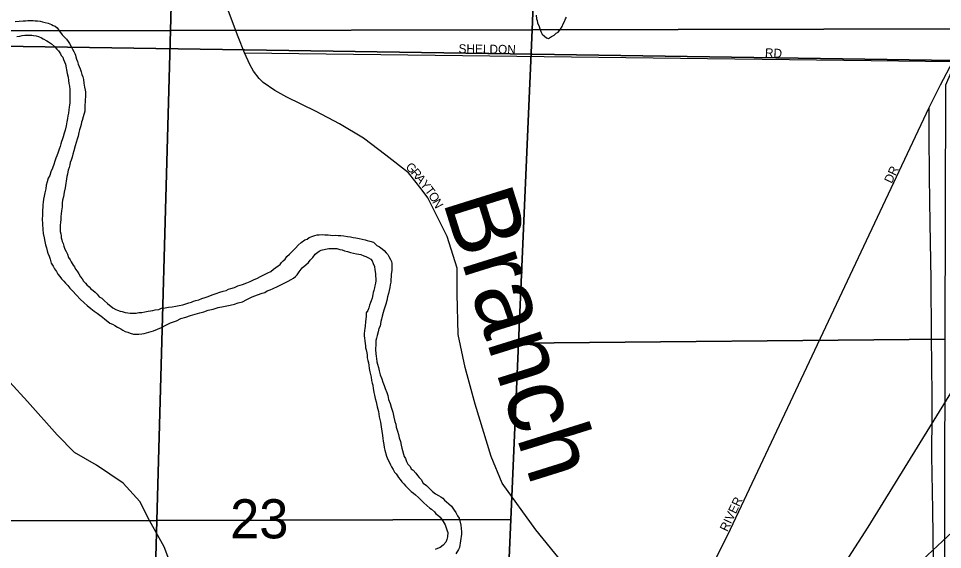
# Model space of a CAD drawing. Extents: x 2010165 to 2382125, y 1060529 to 1407316.
# Drawn here: x 2140939 to 2146157, y 1232726 to 1235726 of the extents above; entities that cross this region are included whole.
import ezdxf

# ---------------------------------------------------------------- set-up
doc = ezdxf.new("R2010")
doc.units = 0
for name, color, linetype in [('GM_X_City_Street', 7, 'Continuous'), ('GM_X_City_Street_Text', 7, 'Continuous'), ('GM_X_Corporation', 7, 'Continuous'), ('GM_X_Major_River', 7, 'Continuous'), ('GM_X_Major_River_Text', 7, 'Continuous'), ('GM_X_Minor_Lake', 7, 'Continuous'), ('GM_X_Rail_Line', 7, 'Continuous'), ('GM_X_Section', 7, 'Continuous'), ('GM_X_Section_Text', 7, 'Continuous'), ('GM_X_State_Route', 7, 'Continuous')]:
    doc.layers.add(name, color=color, linetype=linetype)

msp = doc.modelspace()

# ---------------------------------------------------------------- linework, layer by layer
at = {"layer": 'GM_X_City_Street'}
for points in [[(2142215.9, 1235531), (2142179.9, 1235622.2), (2142124.6, 1235766.7), (2142026.7, 1236037), (2141940.2, 1236277), (2141912, 1236344.5), (2141888.2, 1236376.8), (2141866.2, 1236394.9)], [(2144009.7, 1232655.3), (2143859.6, 1232837.2), (2143669.5, 1233101.4), (2143607.6, 1233252.4), (2143518, 1233547.7), (2143461.3, 1233754.5), (2143421.8, 1233941.3), (2143415.4, 1234170.9), (2143415.4, 1234316.3), (2143359.3, 1234494.9), (2143250.6, 1234712.1), (2143212.7, 1234763.5), (2143140.7, 1234853.3), (2143013.5, 1234954.5), (2142886.8, 1235049.1), (2142752.1, 1235131), (2142620.5, 1235200), (2142454.9, 1235281.4), (2142386.3, 1235318.7), (2142320.6, 1235363.7), (2142298.1, 1235387.7), (2142266.4, 1235428.2), (2142244.7, 1235466), (2142215.9, 1235531)], [(2142215.9, 1235531), (2146214.3, 1235483.3)], [(2143869.2, 1229367.1), (2143460.8, 1230156), (2143301.8, 1230460.3), (2143187.6, 1230770.6), (2143171.3, 1230819.6), (2143165.9, 1230857.7), (2143171.3, 1230890.4), (2143171.3, 1230923), (2143204, 1230966.6), (2143274.8, 1231053.7), (2143911.8, 1231538), (2144293.9, 1231811), (2144500.5, 1231991.2), (2144574.7, 1232072.4), (2144945.5, 1232809), (2146080.9, 1235222.3)], [(2142509.6, 1230902.3), (2142347.9, 1231178.8), (2142270.7, 1231341.5), (2142189.9, 1231576.2), (2142109.1, 1231823), (2141937.3, 1232254.6), (2141814.9, 1232601.7), (2141761.6, 1232742.2), (2141678.4, 1232890.8), (2141624.9, 1232997.2), (2141529.4, 1233101.8), (2141379.9, 1233202.6), (2141256.2, 1233273.3), (2141156.7, 1233373.8), (2140989.6, 1233562.9), (2140788.7, 1233780.1), (2140591.8, 1234009.3), (2140440.6, 1234168.2), (2140245.6, 1234371.4), (2140096.5, 1234495.9), (2139774, 1234723.1), (2139743.3, 1234740.9)]]:
    msp.add_lwpolyline(points, dxfattribs=at)
at = {"layer": 'GM_X_Corporation'}
for points in [[(2140088.5, 1235580.6), (2144964.8, 1235507), (2148854.5, 1235448.2), (2148874.7, 1235434.6), (2148873.5, 1235400.1), (2148869.6, 1235286.1), (2147269.1, 1233776.3), (2147234.9, 1231822.9), (2148765.2, 1231787.5), (2148745.5, 1231049.3), (2149128.1, 1231036.9), (2149132.9, 1230996.9), (2149293, 1230998.1), (2149288.5, 1230921.9), (2149542.9, 1230917), (2149522.2, 1230182.2), (2149485.3, 1229201.7)], [(2156094.2, 1235245.1), (2149217.1, 1235433.5), (2149115.3, 1235421.4), (2149051.6, 1235398.1), (2148873.5, 1235400.1), (2148874.7, 1235434.6), (2148854.5, 1235448.2), (2144964.8, 1235507), (2140088.5, 1235580.6)]]:
    msp.add_lwpolyline(points, dxfattribs=at)
at = {"layer": 'GM_X_Major_River'}
for points in [[(2140920.4, 1235708.5), (2140964.5, 1235713.4), (2140978.5, 1235713.6), (2140992.6, 1235713.9), (2141002.6, 1235714.1), (2141012.6, 1235714.3), (2141022.7, 1235714.5), (2141032.7, 1235712.7), (2141046.8, 1235712.9), (2141060.9, 1235711.2), (2141075, 1235707.5), (2141089.1, 1235703.7), (2141107.2, 1235700.1), (2141125.4, 1235692.4), (2141135.6, 1235686.6), (2141145.7, 1235682.7), (2141157.9, 1235672.9), (2141170.3, 1235655.1), (2141184.7, 1235633.3), (2141199, 1235619.5), (2141209.2, 1235609.7), (2141219.5, 1235595.8), (2141227.8, 1235584), (2141238.2, 1235564.1), (2141244.4, 1235552.2), (2141250.6, 1235540.2), (2141256.9, 1235528.3), (2141261.1, 1235518.4), (2141263.3, 1235508.4), (2141267.5, 1235496.4), (2141271.8, 1235482.5), (2141276.1, 1235468.5), (2141286.6, 1235440.6), (2141292.9, 1235424.7), (2141297.2, 1235408.7), (2141301.5, 1235396.7), (2141305.8, 1235380.8), (2141308.2, 1235360.8), (2141310.4, 1235348.8), (2141312.6, 1235338.8), (2141314.9, 1235320.7), (2141317.1, 1235310.8), (2141317.4, 1235296.7), (2141317.6, 1235282.7), (2141315.9, 1235268.6)], [(2140930, 1235624.4), (2140946, 1235626.7), (2140960, 1235629), (2140974, 1235631.3), (2140986.1, 1235631.5), (2141004.1, 1235631.9), (2141014.2, 1235632.1), (2141024.2, 1235630.2), (2141038.3, 1235628.5), (2141052.4, 1235624.8), (2141068.6, 1235617), (2141078.8, 1235611.2), (2141099, 1235599.6), (2141109.2, 1235593.7), (2141125.5, 1235582), (2141141.8, 1235568.3), (2141156.1, 1235552.5), (2141164.3, 1235542.6), (2141176.7, 1235526.8), (2141180.9, 1235516.8), (2141189.1, 1235507), (2141193.3, 1235495), (2141199.6, 1235481.1), (2141203.9, 1235467.1), (2141214.8, 1235415.1), (2141219.2, 1235395.2), (2141221.6, 1235375.1), (2141223.9, 1235359.1), (2141226.2, 1235343.1), (2141228.6, 1235325.1), (2141228.9, 1235309.1), (2141229.1, 1235295), (2141229.4, 1235281), (2141229.7, 1235264.9), (2141228, 1235248.8), (2141226.2, 1235236.8), (2141224.4, 1235224.7), (2141222.7, 1235210.6), (2141221, 1235190.5), (2141217.3, 1235176.4), (2141215.6, 1235160.3), (2141211.9, 1235142.2), (2141208.3, 1235120), (2141202.7, 1235095.8)], [(2141315.9, 1235268.6), (2141316.2, 1235252.5), (2141314.4, 1235238.4), (2141313.1, 1235202.3), (2141303.7, 1235170), (2141298, 1235149.8), (2141294.2, 1235139.7), (2141292.4, 1235127.7), (2141288.7, 1235113.5), (2141282.9, 1235097.4), (2141279.2, 1235081.2), (2141275.6, 1235061.1), (2141269.9, 1235044.9), (2141264.2, 1235024.8), (2141258.5, 1235006.6), (2141251, 1234978.4), (2141245.4, 1234960.2), (2141241.7, 1234942.1), (2141236, 1234925.9), (2141230.2, 1234911.7), (2141228.4, 1234899.7), (2141224.7, 1234883.5), (2141219, 1234869.4), (2141217.1, 1234859.3), (2141215.3, 1234847.2), (2141211.6, 1234833.1), (2141202.8, 1234768.7), (2141197.2, 1234744.5), (2141193.7, 1234718.4), (2141188, 1234700.2), (2141186.3, 1234682.1), (2141184.7, 1234662), (2141181.1, 1234639.9), (2141179.4, 1234621.8), (2141177.6, 1234607.7), (2141177.9, 1234591.7), (2141176.3, 1234571.6), (2141174.5, 1234559.5), (2141174.8, 1234545.4), (2141175, 1234535.4), (2141175.2, 1234523.4), (2141177.5, 1234509.4), (2141179.7, 1234497.4), (2141179.9, 1234487.3), (2141184.1, 1234475.4), (2141186.3, 1234465.4), (2141190.5, 1234455.4), (2141194.8, 1234439.5), (2141201.1, 1234423.5), (2141207.4, 1234409.6), (2141215.7, 1234393.7), (2141222.1, 1234375.8), (2141230.4, 1234361.9), (2141236.6, 1234352), (2141247, 1234332.1), (2141255.2, 1234322.2), (2141261.4, 1234310.3), (2141269.7, 1234298.4), (2141280, 1234282.6), (2141288.3, 1234266.7), (2141298.6, 1234254.8), (2141306.8, 1234242.9), (2141317.1, 1234231.1), (2141325.3, 1234221.2), (2141337.5, 1234209.4), (2141347.8, 1234199.6), (2141360, 1234189.8), (2141372.2, 1234180), (2141382.5, 1234168.1), (2141394.8, 1234154.3), (2141408.9, 1234146.6), (2141425.3, 1234130.8), (2141441.6, 1234115.1), (2141472.2, 1234091.6), (2141488.4, 1234081.9), (2141498.5, 1234078), (2141512.7, 1234072.3), (2141524.7, 1234070.5), (2141540.9, 1234064.8), (2141557, 1234063.1), (2141569.1, 1234061.3), (2141579.1, 1234061.5), (2141589.1, 1234061.7), (2141603.2, 1234062), (2141619.2, 1234064.3), (2141635.2, 1234064.6), (2141653.2, 1234069), (2141671.2, 1234073.3), (2141697.2, 1234075.8), (2141711.2, 1234080.1), (2141731.2, 1234082.5), (2141747.2, 1234088.8), (2141767.2, 1234091.2), (2141785.2, 1234095.6), (2141807.2, 1234098), (2141827.2, 1234100.4), (2141847.2, 1234104.8), (2141867.2, 1234109.2), (2141883.2, 1234113.5), (2141901.1, 1234119.9), (2141915.1, 1234124.1)], [(2141202.7, 1235095.8), (2141197, 1235077.7), (2141191.4, 1235057.5), (2141185.7, 1235041.3), (2141181.8, 1235031.2), (2141178.1, 1235017.1), (2141174.3, 1235003), (2141168.6, 1234986.8), (2141162.9, 1234970.6), (2141155.2, 1234950.4), (2141149.5, 1234936.3), (2141143.8, 1234920.1), (2141138.1, 1234901.9), (2141130.5, 1234879.7), (2141120.8, 1234859.5), (2141115.2, 1234839.3), (2141107.4, 1234823.1), (2141101.8, 1234802.9), (2141096.1, 1234784.8), (2141092.5, 1234764.6), (2141086.9, 1234740.4), (2141083.2, 1234722.3), (2141079.5, 1234706.2), (2141077.8, 1234688.1), (2141076.1, 1234674), (2141076.3, 1234659.9), (2141074.6, 1234643.9), (2141074.9, 1234627.8), (2141075.2, 1234613.8), (2141073.6, 1234593.7), (2141076.7, 1234533.5), (2141079.1, 1234511.5), (2141083.6, 1234487.5), (2141088, 1234465.5), (2141092.3, 1234447.5), (2141096.7, 1234429.6), (2141101, 1234413.6), (2141105.3, 1234399.6), (2141111.6, 1234383.7), (2141117.9, 1234365.7), (2141124.3, 1234343.8), (2141134.7, 1234325.9), (2141143, 1234312), (2141153.3, 1234296.2), (2141161.6, 1234282.3), (2141171.9, 1234268.4), (2141182.2, 1234254.6), (2141194.5, 1234242.8), (2141204.7, 1234230.9), (2141217, 1234217.1), (2141229.3, 1234203.3), (2141243.6, 1234187.5), (2141266.2, 1234163.9), (2141286.7, 1234140.2), (2141309.1, 1234120.6), (2141327.4, 1234104.9), (2141347.8, 1234087.2), (2141366.2, 1234073.5), (2141382.4, 1234061.8), (2141398.7, 1234050), (2141413, 1234038.3), (2141427.2, 1234026.5), (2141443.5, 1234014.8), (2141455.7, 1234005), (2141469.9, 1233999.2), (2141482.1, 1233991.4), (2141498.3, 1233981.7), (2141516.5, 1233972), (2141528.7, 1233966.2), (2141540.9, 1233958.4), (2141557, 1233954.7), (2141569.1, 1233948.9), (2141589.3, 1233943.3), (2141603.4, 1233943.6), (2141619.4, 1233941.9), (2141635.4, 1233944.2), (2141649.5, 1233946.5), (2141701.4, 1233961.5), (2141723.3, 1233970), (2141747.2, 1233980.5), (2141771, 1233993), (2141796.8, 1234007.5), (2141830.7, 1234018.2), (2141856.6, 1234030.7), (2141884.5, 1234039.3), (2141910.5, 1234047.8), (2141936.4, 1234056.3), (2141962.4, 1234062.8), (2141986.3, 1234069.3), (2142010.2, 1234077.8), (2142038.2, 1234084.4), (2142066.1, 1234092.9), (2142096.1, 1234099.5), (2142134.1, 1234106.3), (2142158.1, 1234112.8), (2142180.1, 1234119.2), (2142204, 1234125.7), (2142227.9, 1234138.2), (2142257.7, 1234152.8), (2142289.6, 1234165.4), (2142315.5, 1234174)], [(2141915.1, 1234124.1), (2141927, 1234128.4), (2141941, 1234132.7), (2141957, 1234137), (2141974.9, 1234143.4), (2141992.8, 1234149.7), (2142010.8, 1234156.1), (2142032.7, 1234164.5), (2142054.6, 1234173), (2142076.6, 1234179.4), (2142094.5, 1234185.8), (2142112.5, 1234190.1), (2142124.4, 1234196.4), (2142138.4, 1234200.7), (2142158.4, 1234207.1), (2142178.3, 1234215.5), (2142204.2, 1234224), (2142228.1, 1234232.5), (2142248, 1234240.9), (2142265.9, 1234249.3), (2142287.8, 1234259.7), (2142305.7, 1234268.1), (2142347.5, 1234289), (2142363.4, 1234297.3), (2142379.2, 1234309.6), (2142393, 1234319.9), (2142404.9, 1234328.2), (2142416.8, 1234336.5), (2142424.7, 1234346.6), (2142434.5, 1234356.9), (2142444.4, 1234367.1), (2142454.1, 1234381.3), (2142470, 1234393.7), (2142493.6, 1234418.2), (2142503.4, 1234428.4), (2142519.2, 1234444.8), (2142534.9, 1234461.1), (2142556.7, 1234475.6), (2142568.7, 1234479.8), (2142580.6, 1234488.1), (2142600.5, 1234496.5), (2142612.5, 1234500.8), (2142626.5, 1234503), (2142636.5, 1234503.2), (2142656.5, 1234505.6), (2142668.6, 1234503.8), (2142688.6, 1234504.2), (2142700.7, 1234502.4), (2142714.8, 1234500.7), (2142730.8, 1234501), (2142744.9, 1234499.3), (2142759, 1234499.6), (2142777.1, 1234497.9), (2142797.2, 1234494.3), (2142813.3, 1234492.6), (2142829.4, 1234488.9), (2142843.5, 1234487.1), (2142863.6, 1234483.5), (2142879.7, 1234479.8), (2142895.9, 1234476.1), (2142908, 1234472.3), (2142922.1, 1234468.6), (2142944.3, 1234463), (2142962.7, 1234443.2), (2142976.9, 1234435.5), (2142993.2, 1234423.8), (2143003.3, 1234415.9), (2143015.6, 1234402.1), (2143023.8, 1234392.2), (2143030, 1234382.3), (2143040.4, 1234364.5), (2143044.6, 1234352.5), (2143046.8, 1234342.5), (2143047.2, 1234322.4), (2143047.4, 1234312.4), (2143047.6, 1234302.4), (2143043.9, 1234282.3), (2143044.2, 1234268.2), (2143042.5, 1234252.1), (2143040.8, 1234236), (2143037, 1234221.9), (2143035.3, 1234205.8), (2143031.6, 1234189.7), (2143027.9, 1234171.6), (2143022.2, 1234153.4), (2143018.6, 1234133.3), (2143013, 1234113.1), (2143007.3, 1234094.9), (2143001.6, 1234078.8), (2142997.8, 1234064.6), (2142992.2, 1234044.5), (2142988.4, 1234028.3), (2142984.7, 1234014.2), (2142981.2, 1233988.1), (2142973.4, 1233973.9), (2142969.7, 1233955.7), (2142964.1, 1233935.6), (2142960.4, 1233919.4), (2142956.6, 1233907.3), (2142956.9, 1233889.3), (2142955.6, 1233853.1)], [(2142315.5, 1234174), (2142329.5, 1234178.2), (2142343.4, 1234186.6), (2142359.3, 1234192.9), (2142377.2, 1234201.2), (2142401.1, 1234211.7), (2142421, 1234222.2), (2142442.8, 1234232.6), (2142462.7, 1234243), (2142478.6, 1234251.3), (2142492.5, 1234259.6), (2142502.4, 1234267.9), (2142512.2, 1234278.1), (2142524, 1234294.4), (2142541.6, 1234316.8), (2142561.3, 1234335.2), (2142577.2, 1234347.6), (2142587, 1234359.8), (2142600.7, 1234376.1), (2142614.4, 1234394.4), (2142636.2, 1234410.9), (2142648.1, 1234417.1), (2142672.1, 1234423.6), (2142692.1, 1234426), (2142714.2, 1234426.4), (2142736.2, 1234426.9), (2142754.4, 1234421.2), (2142766.5, 1234419.4), (2142780.6, 1234413.7), (2142796.7, 1234410), (2142812.9, 1234404.3), (2142831, 1234400.6), (2142847.2, 1234396.9), (2142861.2, 1234395.1), (2142871.3, 1234393.3), (2142889.5, 1234385.7), (2142899.6, 1234381.8), (2142915.8, 1234374.1), (2142928, 1234366.3), (2142936.2, 1234356.4), (2142942.5, 1234342.5), (2142948.8, 1234324.6), (2142951.2, 1234306.6), (2142955.6, 1234284.6), (2142955.9, 1234268.5), (2142956.1, 1234258.5), (2142956.3, 1234244.4), (2142954.6, 1234230.4), (2142950.8, 1234216.3), (2142949.1, 1234204.2), (2142945.3, 1234190.1), (2142941.5, 1234177.9), (2142939.7, 1234165.9), (2142936.1, 1234145.7), (2142930.3, 1234131.6), (2142926.5, 1234121.5), (2142920.8, 1234107.3), (2142917, 1234091.2), (2142911.3, 1234077), (2142901.5, 1234062.8), (2142901.9, 1234042.7), (2142898.4, 1234014.6), (2142896.9, 1233988.4), (2142895.1, 1233974.4), (2142893.3, 1233964.3), (2142891.7, 1233944.2), (2142891.9, 1233934.2), (2142892.1, 1233920.1), (2142894.4, 1233904.1), (2142896.7, 1233888.1), (2142898.9, 1233878.1), (2142899.1, 1233866.1), (2142901.4, 1233854.1), (2142905.7, 1233838.1), (2142908, 1233824.1), (2142908.3, 1233808.1), (2142912.5, 1233794.1), (2142914.8, 1233780.1), (2142917, 1233768.1), (2142919.4, 1233748.1), (2142923.7, 1233730.1), (2142926, 1233714.1), (2142930.3, 1233700.1), (2142932.7, 1233680.1), (2142937, 1233666.1), (2142939.2, 1233654.1), (2142941.5, 1233636.1), (2142943.7, 1233626.1), (2142946, 1233614.1), (2142950.3, 1233598.1), (2142952.6, 1233580.1), (2142959, 1233560.2), (2142963.5, 1233532.2), (2142972, 1233506.2), (2142976.6, 1233476.2), (2142983.2, 1233446.3), (2142987.7, 1233418.3), (2142990.2, 1233394.2), (2142994.6, 1233370.2), (2142996.9, 1233354.2), (2142999.2, 1233338.2)], [(2142955.6, 1233853.1), (2142958.3, 1233817), (2142960.5, 1233805), (2142962.8, 1233787), (2142967.1, 1233773.1), (2142971.4, 1233755.1), (2142975.8, 1233735.1), (2142982.2, 1233713.1), (2142990.7, 1233691.2), (2142997.1, 1233671.3), (2143003.4, 1233653.3), (2143009.8, 1233635.4), (2143018.2, 1233613.5), (2143024.6, 1233595.6), (2143029, 1233573.6), (2143037.4, 1233551.7), (2143043.8, 1233529.7), (2143052.4, 1233501.8), (2143058.9, 1233473.8), (2143063.4, 1233449.8), (2143069.7, 1233433.9), (2143072, 1233417.9), (2143076.3, 1233405.9), (2143078.5, 1233393.9), (2143084.8, 1233376), (2143089.2, 1233358), (2143095.6, 1233336), (2143100, 1233316.1), (2143104.3, 1233298.1), (2143117.2, 1233252.2), (2143123.5, 1233240.2), (2143129.8, 1233224.3), (2143138.1, 1233208.4), (2143150.4, 1233194.6), (2143156.6, 1233182.7), (2143166.8, 1233174.8), (2143183.2, 1233157.1), (2143191.4, 1233145.2), (2143201.7, 1233133.4), (2143212, 1233121.5), (2143224.4, 1233101.7), (2143242.7, 1233088), (2143252.9, 1233078.2), (2143263.1, 1233066.3), (2143277.4, 1233054.6), (2143293.7, 1233040.8), (2143310, 1233031.1), (2143324.2, 1233023.3), (2143334.3, 1233015.5), (2143344.5, 1233005.7), (2143356.8, 1232995.9), (2143369, 1232984.1), (2143383.3, 1232970.3), (2143399.8, 1232948.5), (2143408.1, 1232934.6), (2143418.4, 1232916.8), (2143426.7, 1232902.9), (2143437.5, 1232863), (2143440.2, 1232826.9), (2143440.4, 1232812.9), (2143429.8, 1232738.4), (2143424, 1232726.2), (2143408.4, 1232701.9)], [(2142999.2, 1233338.2), (2143001.6, 1233320.2), (2143003.9, 1233302.2), (2143008.2, 1233288.2), (2143016.8, 1233254.3), (2143025.2, 1233234.3), (2143031.5, 1233222.4), (2143039.8, 1233204.5), (2143046.1, 1233192.6), (2143054.4, 1233178.7), (2143062.7, 1233162.8), (2143070.9, 1233152.9), (2143079.1, 1233143.1), (2143085.3, 1233133.2), (2143093.6, 1233121.3), (2143103.8, 1233109.4), (2143114.1, 1233097.6), (2143124.3, 1233085.7), (2143134.5, 1233075.9), (2143146.8, 1233064.1), (2143157, 1233054.3), (2143169.2, 1233044.5), (2143181.5, 1233034.7), (2143197.8, 1233020.9), (2143208, 1233011.1), (2143218.2, 1232999.2), (2143228.5, 1232989.4), (2143244.8, 1232975.7), (2143261.1, 1232959.9), (2143271.3, 1232954.1), (2143287.6, 1232938.4), (2143295.8, 1232928.5), (2143306, 1232922.7), (2143320.2, 1232908.9), (2143330.5, 1232895), (2143336.8, 1232885.1), (2143343, 1232875.2), (2143349.2, 1232865.3), (2143359.8, 1232831.4), (2143364, 1232821.4), (2143362.5, 1232797.3), (2143358.7, 1232783.2), (2143353, 1232767), (2143337.2, 1232750.7), (2143319.4, 1232738.3), (2143305.5, 1232732), (2143291.5, 1232725.7)]]:
    msp.add_lwpolyline(points, dxfattribs=at)
at = {"layer": 'GM_X_Minor_Lake'}
msp.add_lwpolyline([(2143861.7, 1235744.8), (2143864, 1235724.8), (2143868.2, 1235714.8), (2143870.5, 1235700.8), (2143878.9, 1235680.9), (2143883.2, 1235667), (2143889.4, 1235653.1), (2143895.8, 1235637.1), (2143910, 1235625.3), (2143920.2, 1235617.5), (2143932.3, 1235613.7), (2143948.2, 1235624.1), (2143964.1, 1235632.4), (2143975.9, 1235642.7), (2143985.9, 1235648.9), (2143999.6, 1235665.2), (2144009.3, 1235681.4), (2144015.1, 1235695.6), (2144022.9, 1235709.8), (2144028.6, 1235723.9), (2144034.4, 1235734.1)], dxfattribs=at)
at = {"layer": 'GM_X_Rail_Line'}
for points in [[(2144106.6, 1231241.8), (2144229.6, 1231335.2), (2144420.6, 1231469.2), (2144593.9, 1231598.3), (2144768.9, 1231732.5), (2144893, 1231824.9), (2145010.5, 1231928.2), (2145104.6, 1232021.5), (2145218.7, 1232148.2), (2145340.4, 1232286.4), (2145444.5, 1232419.7), (2145531.1, 1232538), (2145627.8, 1232682.2), (2145736.9, 1232852.9), (2146031, 1233329.5), (2146368.4, 1233874.3), (2146737, 1234469.9), (2146943.7, 1234810.9), (2147365.6, 1235489.3), (2147948.7, 1236435), (2148494.7, 1237318.9), (2149019.9, 1238173.1)], [(2143311.5, 1230572.3), (2143801.8, 1230913.6), (2144064.7, 1231097.2), (2144290.5, 1231255.9), (2144436.9, 1231352.9), (2144581.5, 1231454.1), (2144704, 1231540.9), (2144852.6, 1231644.3), (2144961.3, 1231727.5), (2145059.4, 1231805), (2145165.7, 1231893.7), (2145265.4, 1231976.5), (2145375.8, 1232070.9), (2145584.4, 1232248.8), (2145715.9, 1232365.6), (2146071.7, 1232695.2), (2146213.4, 1232826.8), (2147723.2, 1234264.7), (2148913.3, 1235390.1)]]:
    msp.add_lwpolyline(points, dxfattribs=at)
at = {"layer": 'GM_X_Section'}
for points in [[(2141869.6, 1238367.9), (2141797.8, 1235658.1), (2139732.4, 1235654), (2139740.6, 1235952.8), (2139795.1, 1238150), (2139800.3, 1238385.2)], [(2143946.6, 1238350.5), (2143912, 1237485.9), (2143838.9, 1235662.2), (2141797.8, 1235658.1), (2141869.6, 1238367.9)], [(2143912, 1237485.9), (2146397.7, 1237469.6), (2146311, 1235667.1), (2143838.9, 1235662.2)], [(2139732.4, 1235654), (2141797.8, 1235658.1), (2141720.3, 1232890.9), (2139704.7, 1232886.4), (2139705.7, 1233846.9)], [(2141797.8, 1235658.1), (2143838.9, 1235662.2), (2143762.7, 1233892), (2143719.8, 1232895.4), (2141720.3, 1232890.9)], [(2143838.9, 1235662.2), (2146311, 1235667.1), (2146173.7, 1235349.6), (2146170.5, 1233914.6), (2143762.7, 1233892)], [(2143762.7, 1233892), (2146170.5, 1233914.6), (2146166.5, 1232055.2), (2143682.3, 1232025.4), (2143719.8, 1232895.4)], [(2141720.3, 1232890.9), (2141648.6, 1230264.6), (2141648.1, 1230239.3), (2139686.1, 1230258), (2139691.5, 1230734.2), (2139701.1, 1231653.2), (2139705.6, 1232793.9), (2139704.7, 1232886.4)], [(2143719.8, 1232895.4), (2143682.3, 1232025.4), (2143606.4, 1230260.6), (2143604.9, 1230220.8), (2141648.1, 1230239.3), (2141648.6, 1230264.6), (2141720.3, 1232890.9)]]:
    msp.add_lwpolyline(points, close=True, dxfattribs=at)
at = {"layer": 'GM_X_State_Route'}
for points in [[(2146081, 1235198), (2146080.9, 1235222.3), (2146144.7, 1235350.8), (2146214.3, 1235483.3)], [(2146098.1, 1233505), (2146098.4, 1233598.8), (2146095.3, 1233929.6), (2146092.2, 1234254.3), (2146087.1, 1234566.9), (2146084.3, 1234831.5), (2146081.5, 1235071.9), (2146081, 1235195.4), (2146081, 1235198)], [(2146105.4, 1232658.5), (2146102.6, 1232949.5), (2146097.5, 1233256.1), (2146098.1, 1233491.7), (2146098.1, 1233505)]]:
    msp.add_lwpolyline(points, dxfattribs=at)

# ---------------------------------------------------------------- texts
at = {"layer": 'GM_X_City_Street_Text'}
for s, rotation, p in [('SHELDON', 359.1191, (2143423.6, 1235530.6)), ('RD', 356.9887, (2145153.2, 1235508.5)), ('G', 316.6617, (2143120.9, 1234882.1)), ('R', 309.591, (2143151.8, 1234853.1)), ('DR', 64.7982, (2145870.2, 1234790.4)), ('A', 307.8884, (2143176.8, 1234822.9)), ('Y', 307.8884, (2143203.8, 1234788.2)), ('T', 307.4437, (2143230.8, 1234753.6)), ('O', 301.3798, (2143251.4, 1234726.8)), ('N', 298.041, (2143273.9, 1234689.9)), ('RIVER', 64.6532, (2144941.8, 1232823.6))]:
    msp.add_text(s, height=50, rotation=rotation, dxfattribs=at).set_placement(p)
at = {"layer": 'GM_X_Major_River_Text'}
msp.add_text('Branch', height=400.24, rotation=287.3775, dxfattribs=at).set_placement((2143333, 1234695.6))
at = {"layer": 'GM_X_Section_Text'}
msp.add_text('23', height=221, rotation=0, dxfattribs=at).set_placement((2142134.3, 1232789.1))

doc.saveas('drawing.dxf')
